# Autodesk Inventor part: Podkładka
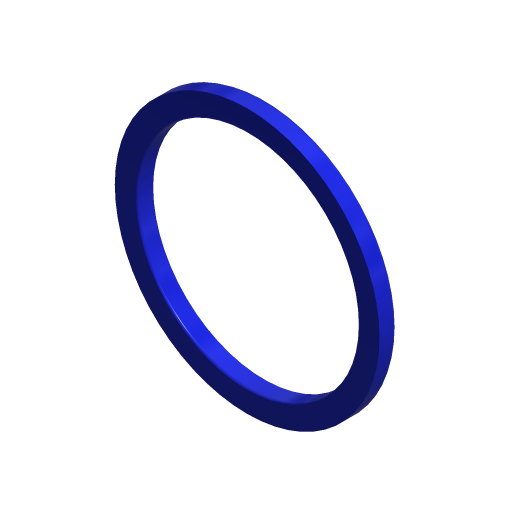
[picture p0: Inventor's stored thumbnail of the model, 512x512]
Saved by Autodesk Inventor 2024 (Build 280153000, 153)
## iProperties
Company: ATC
Shininess: 0.0
Length Units: 11269
Angle Units: 11279
Time Units: 11290
Mass Units: 11283
Length Display Precision: 3
Angle Display Precision: 2
Compacted: True
Created: 2023-03
Part Number: Podkładka
Document SubType Name: Modeling
Designer: Andrzej Jaskulski
Material: Kurs-AJ
Density: 1 g/cm^3
Mass: 0.424834 g
Surface Area: 7.40408 cm^2
Volume: 0.424834 cm^3
Appearance: Niebieska — farba ścienna — lśniąca
Checked By: A.J.
Engr Approved By: Andrzej Jaskulski
Mfg Approved By: Andrzej Jaskulski
Authority: A.J.
Density: 0.0
Volumn: 0.0
Area: 0.0
PropertySet Name: Model Information
Control State: 0
Master: False
Checked Out: False
Title: A.J.: Kurs R2024-MEP
Author: Andrzej Jaskulski
Revision Number: 1/24
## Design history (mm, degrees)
node "Extrusion1" dims "d2" = 2, "d3" = 0
node "Fillet1" dims "d4" = 0.25, "d5" = 0.5
node "Bryła1"
node "Korpusy bryłowe"
node "Korpusy powierzchniowe"
sketch "Sketch1"
  geometry: C1 r 12.5 at (36, 61); C2 r 15 at (36, 61)
  constraints: 2 centre point, 1 coincident
  dimensions: "d0" = 25 diameter of C1; "d1" = 30 diameter of C2
